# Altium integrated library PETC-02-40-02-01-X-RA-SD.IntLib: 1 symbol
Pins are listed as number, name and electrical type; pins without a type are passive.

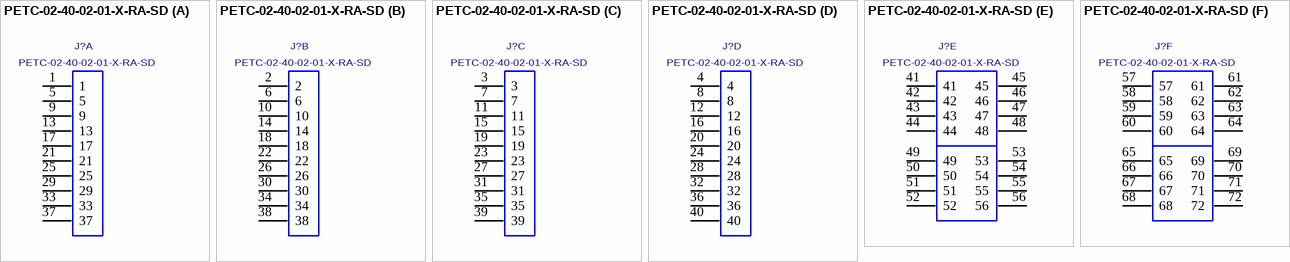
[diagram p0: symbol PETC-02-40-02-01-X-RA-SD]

## PETC-02-40-02-01-X-RA-SD
designator J?
RIGHT ANGLE POWER TERMINAL.; MANUFACTURER: SAMTEC
footprint PETC-02-40-02-01-X-RA-SD
part A pins: 1, 5, 9, 13, 17, 21, 25, 29, 33, 37
part B pins: 2, 6, 10, 14, 18, 22, 26, 30, 34, 38
part C pins: 3, 7, 11, 15, 19, 23, 27, 31, 35, 39
part D pins: 4, 8, 12, 16, 20, 24, 28, 32, 36, 40
part E pins: 41, 42, 43, 44, 45, 46, 47, 48, 49, 50, 51, 52, 53, 54, 55, 56
part F pins: 57, 58, 59, 60, 61, 62, 63, 64, 65, 66, 67, 68, 69, 70, 71, 72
